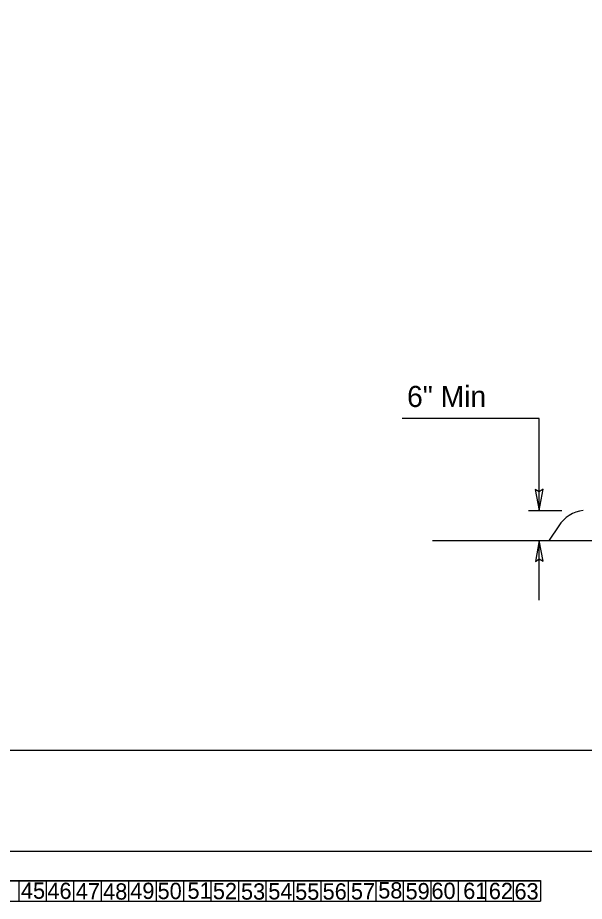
# Model space of a CAD drawing. Extents: x 0 to 2.83, y -0.03 to 1.83.
# Drawn here: x 0.849 to 1.199, y -0.031 to 0.514 of the extents above; entities that cross this region are included whole.
import ezdxf

# ---------------------------------------------------------------- set-up
doc = ezdxf.new("R2010")
doc.units = 0
for name, color, linetype in [('45', 7, 'Continuous'), ('46', 7, 'Continuous'), ('47', 7, 'Continuous'), ('48', 7, 'Continuous'), ('49', 7, 'Continuous'), ('50', 7, 'Continuous'), ('51', 7, 'Continuous'), ('52', 7, 'Continuous'), ('53', 7, 'Continuous'), ('54', 7, 'Continuous'), ('55', 7, 'Continuous'), ('56', 7, 'Continuous'), ('57', 7, 'Continuous'), ('58', 7, 'Continuous'), ('59', 7, 'Continuous'), ('60', 7, 'Continuous'), ('61', 7, 'Continuous'), ('62', 7, 'Continuous'), ('63', 7, 'Continuous')]:
    doc.layers.add(name, color=color, linetype=linetype)

msp = doc.modelspace()

# ---------------------------------------------------------------- linework, layer by layer
at = {"layer": '54'}
for points in [[(1.170918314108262, 0.21038371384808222), (1.173293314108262, 0.2233753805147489), (1.170918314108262, 0.22186704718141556), (1.168518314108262, 0.22322538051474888)], [(1.170918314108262, 0.1918694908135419), (1.168543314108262, 0.17887782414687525), (1.170918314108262, 0.1803861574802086), (1.1733183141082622, 0.17902782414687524)]]:
    msp.add_lwpolyline(points, close=True, dxfattribs=at)
at = {"layer": '55'}
for p, q in [((1.170918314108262, 0.2669453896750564), (1.0864008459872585, 0.2669453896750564)), ((1.170918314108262, 0.21038371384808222), (1.170918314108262, 0.2669453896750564)), ((1.1644101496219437, 0.21038371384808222), (1.1848517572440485, 0.21038371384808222)), ((1.1829585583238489, 0.20074995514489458), (1.176980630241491, 0.19197193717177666)), ((1.10510940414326, 0.1918694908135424), (1.6958996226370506, 0.19186949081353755)), ((1.170918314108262, 0.15492539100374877), (1.170918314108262, 0.1918694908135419))]:
    msp.add_line(p, q, dxfattribs=at)
msp.add_arc((1.2007019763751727, 0.1895973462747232), 0.020957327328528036, 97.3233922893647, 147.8486232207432, dxfattribs=at)
at = {"layer": '62'}
for p, q in [((0.10494166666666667, -0.018041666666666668), (1.1717416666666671, -0.018041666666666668)), ((0.10495500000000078, -0.018096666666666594), (1.1717516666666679, -0.018096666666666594)), ((0.8500083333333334, -0.018041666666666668), (0.8500083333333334, -0.030741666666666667)), ((0.8500216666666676, -0.018096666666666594), (0.8500216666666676, -0.030796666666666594)), ((0.8669416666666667, -0.018041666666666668), (0.8669416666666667, -0.030741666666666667)), ((0.8669516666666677, -0.018096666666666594), (0.8669516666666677, -0.030796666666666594)), ((0.8838750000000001, -0.018041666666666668), (0.8838750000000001, -0.030741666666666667)), ((0.883885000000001, -0.018096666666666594), (0.883885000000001, -0.030796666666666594)), ((0.9008083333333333, -0.018041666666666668), (0.9008083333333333, -0.030741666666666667)), ((0.9008183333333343, -0.018096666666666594), (0.9008183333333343, -0.030796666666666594)), ((0.9177416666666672, -0.018041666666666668), (0.9177416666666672, -0.030741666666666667)), ((0.9177516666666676, -0.018096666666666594), (0.9177516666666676, -0.030796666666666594)), ((0.9346750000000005, -0.018041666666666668), (0.9346750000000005, -0.030741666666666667)), ((0.934685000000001, -0.018096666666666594), (0.934685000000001, -0.030796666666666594)), ((0.9516083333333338, -0.018041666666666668), (0.9516083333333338, -0.030741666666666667)), ((0.9516183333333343, -0.018096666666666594), (0.9516183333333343, -0.030796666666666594)), ((0.9685416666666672, -0.018041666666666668), (0.9685416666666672, -0.030741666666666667)), ((0.9685516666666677, -0.018096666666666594), (0.9685516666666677, -0.030796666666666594)), ((0.9854750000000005, -0.018041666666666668), (0.9854750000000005, -0.030741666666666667)), ((0.9854850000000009, -0.018096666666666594), (0.9854850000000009, -0.030796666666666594)), ((1.0024083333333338, -0.018041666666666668), (1.0024083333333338, -0.030741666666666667)), ((1.0024183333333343, -0.018096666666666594), (1.0024183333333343, -0.030796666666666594)), ((1.0193416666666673, -0.018041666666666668), (1.0193416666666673, -0.030741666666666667)), ((1.0193516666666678, -0.018096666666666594), (1.0193516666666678, -0.030796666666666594)), ((1.0362750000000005, -0.018041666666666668), (1.0362750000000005, -0.030741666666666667)), ((1.036285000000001, -0.018096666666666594), (1.036285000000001, -0.030796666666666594)), ((1.053208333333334, -0.018041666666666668), (1.053208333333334, -0.030741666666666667)), ((1.0532183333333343, -0.018096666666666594), (1.0532183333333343, -0.030796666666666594)), ((1.0701416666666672, -0.018041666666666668), (1.0701416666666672, -0.030741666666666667)), ((1.0701516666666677, -0.018096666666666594), (1.0701516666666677, -0.030796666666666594)), ((1.0870750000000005, -0.018041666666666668), (1.0870750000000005, -0.030741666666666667)), ((1.087085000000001, -0.018096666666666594), (1.087085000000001, -0.030796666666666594)), ((1.104008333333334, -0.018041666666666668), (1.104008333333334, -0.030741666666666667)), ((1.1040183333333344, -0.018096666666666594), (1.1040183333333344, -0.030796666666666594)), ((1.1209416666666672, -0.018041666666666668), (1.1209416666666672, -0.030741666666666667)), ((1.1209516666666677, -0.018096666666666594), (1.1209516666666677, -0.030796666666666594)), ((1.1378750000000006, -0.018041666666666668), (1.1378750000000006, -0.030741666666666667)), ((1.1378850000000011, -0.018096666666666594), (1.1378850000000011, -0.030796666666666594)), ((1.1548083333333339, -0.018041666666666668), (1.1548083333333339, -0.030741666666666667)), ((1.1548183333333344, -0.018096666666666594), (1.1548183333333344, -0.030796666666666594)), ((1.1717416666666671, -0.018041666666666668), (1.1717416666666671, -0.030741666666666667)), ((1.1717516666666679, -0.018096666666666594), (1.1717516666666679, -0.030796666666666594)), ((0.10494166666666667, -0.030741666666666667), (1.1717416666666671, -0.030741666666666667)), ((0.10495500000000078, -0.030796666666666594), (1.1717516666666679, -0.030796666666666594))]:
    msp.add_line(p, q, dxfattribs=at)
at = {"layer": '63'}
msp.add_line((2.833333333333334, 0), (0, 0), dxfattribs=at)
msp.add_lwpolyline([(2.729175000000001, 1.770775), (0.10417500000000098, 1.770775), (0.10417500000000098, 0.06244166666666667), (2.729175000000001, 0.06244166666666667)], close=True, dxfattribs=at)

# ---------------------------------------------------------------- texts
at = {"layer": '45'}
for height, p in [(0.00999995, (0.8513916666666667, -0.029183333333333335)), (0.009999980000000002, (0.8514016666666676, -0.02923666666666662))]:
    msp.add_text('45', height=height, dxfattribs=at).set_placement(p)
at = {"layer": '46'}
for height, p in [(0.00999995, (0.8677, -0.029291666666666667)), (0.009999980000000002, (0.8677116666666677, -0.02934999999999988))]:
    msp.add_text('46', height=height, dxfattribs=at).set_placement(p)
at = {"layer": '47'}
for height, p in [(0.00999995, (0.8852000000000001, -0.029583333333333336)), (0.009999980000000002, (0.8852150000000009, -0.02963666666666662))]:
    msp.add_text('47', height=height, dxfattribs=at).set_placement(p)
at = {"layer": '48'}
for height, p in [(0.00999995, (0.90205, -0.02969166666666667)), (0.009999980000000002, (0.9020616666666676, -0.02974999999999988))]:
    msp.add_text('48', height=height, dxfattribs=at).set_placement(p)
at = {"layer": '49'}
for height, p in [(0.00999995, (0.9188166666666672, -0.029291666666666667)), (0.009999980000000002, (0.918825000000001, -0.029346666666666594))]:
    msp.add_text('49', height=height, dxfattribs=at).set_placement(p)
at = {"layer": '50'}
for height, p in [(0.00999995, (0.9356250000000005, -0.029383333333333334)), (0.009999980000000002, (0.9356383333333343, -0.029436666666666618))]:
    msp.add_text('50', height=height, dxfattribs=at).set_placement(p)
at = {"layer": '51'}
for height, p in [(0.00999995, (0.9540666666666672, -0.029175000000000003)), (0.009999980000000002, (0.9540816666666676, -0.029233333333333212))]:
    msp.add_text('51', height=height, dxfattribs=at).set_placement(p)
at = {"layer": '52'}
for height, p in [(0.00999995, (0.9697166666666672, -0.029458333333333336)), (0.009999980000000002, (0.9697250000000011, -0.029516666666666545))]:
    msp.add_text('52', height=height, dxfattribs=at).set_placement(p)
at = {"layer": '53'}
for height, p in [(0.00999995, (0.9870500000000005, -0.0297)), (0.009999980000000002, (0.987065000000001, -0.02975666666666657))]:
    msp.add_text('53', height=height, dxfattribs=at).set_placement(p)
at = {"layer": '54'}
for height, p in [(0.00999995, (1.0039000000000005, -0.029583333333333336)), (0.009999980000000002, (1.003915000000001, -0.02963666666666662))]:
    msp.add_text('54', height=height, dxfattribs=at).set_placement(p)
at = {"layer": '55'}
for height, p in [(0.00999995, (1.0204666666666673, -0.029783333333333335)), (0.009999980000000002, (1.020475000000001, -0.029839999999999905))]:
    msp.add_text('55', height=height, dxfattribs=at).set_placement(p)
at = {"layer": '56'}
for height, p in [(0.00999995, (1.0373916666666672, -0.029666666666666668)), (0.009999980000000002, (1.037405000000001, -0.029723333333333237))]:
    msp.add_text('56', height=height, dxfattribs=at).set_placement(p)
at = {"layer": '57'}
for s, height, p in [('6" Min', 0.013020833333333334, (1.0894484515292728, 0.2741279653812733)), ('57', 0.00999995, (1.0548166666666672, -0.02955)), ('57', 0.009999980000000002, (1.0548316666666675, -0.02960666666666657))]:
    msp.add_text(s, height=height, dxfattribs=at).set_placement(p)
at = {"layer": '58'}
for height, p in [(0.00999995, (1.0716666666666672, -0.028975)), (0.009999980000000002, (1.0716816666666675, -0.029029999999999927))]:
    msp.add_text('58', height=height, dxfattribs=at).set_placement(p)
at = {"layer": '59'}
for height, p in [(0.00999995, (1.0885166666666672, -0.029500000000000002)), (0.009999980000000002, (1.0885316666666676, -0.029553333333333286))]:
    msp.add_text('59', height=height, dxfattribs=at).set_placement(p)
at = {"layer": '60'}
for height, p in [(0.00999995, (1.1044750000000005, -0.029291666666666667)), (0.009999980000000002, (1.1044883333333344, -0.02934999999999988))]:
    msp.add_text('60', height=height, dxfattribs=at).set_placement(p)
at = {"layer": '61'}
for height, p in [(0.00999995, (1.1240583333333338, -0.029291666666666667)), (0.009999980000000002, (1.1240683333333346, -0.02934999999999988))]:
    msp.add_text('61', height=height, dxfattribs=at).set_placement(p)
at = {"layer": '62'}
for height, p in [(0.00999995, (1.1398416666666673, -0.029375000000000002)), (0.009999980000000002, (1.1398550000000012, -0.029433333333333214))]:
    msp.add_text('62', height=height, dxfattribs=at).set_placement(p)
at = {"layer": '63'}
for height, p in [(0.00999995, (1.1556750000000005, -0.029575)), (0.009999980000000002, (1.1556883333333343, -0.029633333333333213))]:
    msp.add_text('63', height=height, dxfattribs=at).set_placement(p)

doc.saveas('drawing.dxf')
